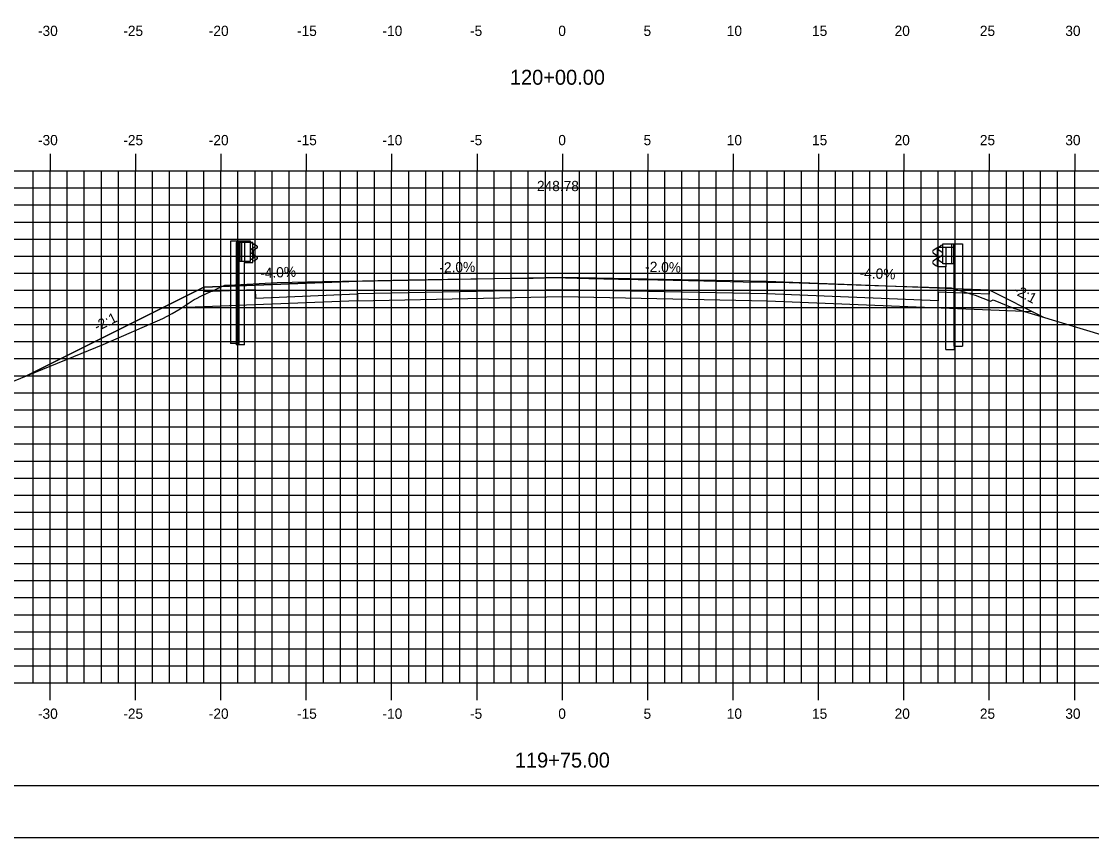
# Model space of a CAD drawing. Extents: x -22 to 1480, y -1511 to 8.
# Drawn here: x 378.2 to 440.9, y -1511.4 to -1463.6 of the extents above; entities that cross this region are included whole.
import ezdxf

# ---------------------------------------------------------------- set-up
doc = ezdxf.new("R2010")
doc.units = 0
for name, color, linetype in [('ANNOTATION', 7, 'Continuous'), ('BORDER', 7, 'Continuous'), ('D_Guardrail_Beam_Lt', 7, 'Continuous'), ('D_Guardrail_Beam_Rt', 7, 'Continuous'), ('D_Roadway_Centerline', 7, 'Continuous'), ('D_Roadway_Centerline_Text', 7, 'Continuous'), ('D_Roadway_Edge_Shoulder', 7, 'Continuous'), ('D_Roadway_Edge_TW', 7, 'Continuous'), ('D_Roadway_SlopeLines', 7, 'Continuous'), ('D_Roadway_SubGrade', 7, 'Continuous'), ('H_V ANNOTATION', 7, 'Continuous'), ('MAJOR', 7, 'Continuous'), ('MINOR', 7, 'Continuous'), ('PLOT BOUNDARY', 7, 'Continuous'), ('S_Guardrail_Beam', 7, 'Continuous'), ('S_Roadway_Centerline', 7, 'Continuous')]:
    doc.layers.add(name, color=color, linetype=linetype)

msp = doc.modelspace()

# ---------------------------------------------------------------- linework, layer by layer
at = {"layer": 'BORDER'}
msp.add_line((334.913, -1508.331), (494.913, -1508.331), dxfattribs=at)
at = {"layer": 'D_Guardrail_Beam_Lt'}
for p, q in [((390.484, -1476.449), (390.484, -1482.449)), ((390.955, -1476.449), (390.484, -1476.449)), ((391.642, -1476.449), (390.955, -1476.449)), ((390.955, -1476.449), (390.955, -1477.616)), ((391.017, -1476.449), (391.017, -1477.616)), ((391.121, -1476.449), (391.121, -1477.616)), ((391.642, -1477.616), (391.642, -1476.449)), ((391.642, -1476.532), (391.716, -1476.547)), ((391.647, -1476.997), (391.647, -1477.067)), ((391.876, -1476.797), (391.68, -1476.933)), ((391.68, -1477.132), (391.876, -1477.268)), ((391.732, -1476.554), (391.876, -1476.654)), ((390.955, -1477.616), (391.642, -1477.616)), ((390.975, -1482.449), (390.975, -1477.616)), ((391.716, -1477.518), (391.642, -1477.532)), ((391.876, -1477.411), (391.732, -1477.511)), ((390.975, -1482.449), (390.484, -1482.449))]:
    msp.add_line(p, q, dxfattribs=at)
for centre, major_axis, start_param, end_param in [((391.725, -1476.997), (-0.0789, 0), 5.323254, 6.283185), ((391.725, -1477.067), (-0.0789, 0), 6.283185, 7.243116), ((391.708, -1476.588), (0.0417, 0), 0.959931, 1.376053), ((391.825, -1476.725), (0.0877, 0), 5.323254, 7.243116), ((391.708, -1477.477), (0.0417, 0), 4.907132, 5.323254), ((391.825, -1477.34), (0.0877, 0), 5.323254, 7.243116)]:
    msp.add_ellipse(centre, major_axis=major_axis, ratio=0.995501, start_param=start_param, end_param=end_param, dxfattribs=at)
at = {"layer": 'D_Guardrail_Beam_Rt'}
for p, q in [((432.094, -1476.714), (431.95, -1476.814)), ((431.95, -1476.957), (432.146, -1477.093)), ((432.184, -1476.692), (432.11, -1476.707)), ((432.179, -1477.157), (432.179, -1477.227)), ((432.184, -1476.609), (432.871, -1476.609)), ((432.184, -1477.776), (432.184, -1476.609)), ((432.705, -1476.609), (432.705, -1477.776)), ((432.809, -1476.609), (432.809, -1477.776)), ((432.871, -1476.609), (433.342, -1476.609)), ((432.871, -1476.609), (432.871, -1477.776)), ((433.342, -1476.609), (433.342, -1482.609)), ((432.146, -1477.292), (431.95, -1477.428)), ((431.95, -1477.571), (432.094, -1477.671)), ((432.11, -1477.678), (432.184, -1477.692)), ((432.871, -1477.776), (432.184, -1477.776)), ((432.85, -1482.609), (432.85, -1477.776)), ((432.85, -1482.609), (433.342, -1482.609))]:
    msp.add_line(p, q, dxfattribs=at)
for centre, major_axis, start_param, end_param in [((432.001, -1476.885), (-0.0877, 0), 5.323254, 7.243116), ((432.118, -1476.748), (-0.0417, 0), 4.907132, 5.323254), ((432.1, -1477.157), (0.0789, 0), 0, 0.959931), ((432.001, -1477.5), (-0.0877, 0), 5.323254, 7.243116), ((432.118, -1477.637), (-0.0417, 0), 0.959931, 1.376053), ((432.1, -1477.227), (0.0789, 0), 5.323254, 6.283185)]:
    msp.add_ellipse(centre, major_axis=major_axis, ratio=0.995501, start_param=start_param, end_param=end_param, dxfattribs=at)
at = {"layer": 'D_Roadway_Centerline'}
msp.add_lwpolyline([(378.558, -1484.33), (388.913, -1479.152), (391.913, -1479.032), (397.913, -1478.792), (409.913, -1478.552), (421.913, -1478.792), (431.913, -1479.192), (434.913, -1479.312)], dxfattribs=at)
at = {"layer": 'D_Roadway_Edge_Shoulder'}
for points in [[(397.913, -1478.792), (391.913, -1479.032), (391.913, -1479.032), (388.913, -1479.152), (388.913, -1479.402), (391.913, -1479.282), (391.913, -1479.282), (391.943, -1479.781), (397.913, -1479.542)], [(421.913, -1478.792), (427.913, -1479.032), (427.913, -1479.032), (434.913, -1479.312), (434.913, -1479.562), (431.913, -1479.442), (431.913, -1479.442), (431.913, -1479.942), (421.903, -1479.542)]]:
    msp.add_lwpolyline(points, close=True, dxfattribs=at)
at = {"layer": 'D_Roadway_Edge_TW'}
msp.add_lwpolyline([(397.913, -1479.542), (397.913, -1478.792), (409.913, -1478.552), (421.913, -1478.792), (421.913, -1479.542), (409.913, -1479.302)], close=True, dxfattribs=at)
at = {"layer": 'D_Roadway_SlopeLines'}
for p, q in [((434.913, -1479.312), (438.085, -1480.899)), ((397.913, -1479.942), (386.413, -1480.402))]:
    msp.add_line(p, q, dxfattribs=at)
msp.add_lwpolyline([(388.913, -1479.152), (378.549, -1484.334)], dxfattribs=at)
at = {"layer": 'D_Roadway_SubGrade'}
msp.add_line((421.913, -1479.942), (437.413, -1480.562), dxfattribs=at)
msp.add_lwpolyline([(421.913, -1479.942), (421.913, -1479.542), (409.913, -1479.302), (397.913, -1479.542), (397.913, -1479.942), (409.913, -1479.702)], close=True, dxfattribs=at)
at = {"layer": 'MAJOR'}
for p, q in [((379.913, -1471.329), (379.913, -1472.331)), ((384.913, -1471.329), (384.913, -1472.331)), ((389.913, -1471.329), (389.913, -1472.331)), ((394.913, -1471.329), (394.913, -1472.331)), ((399.913, -1471.329), (399.913, -1472.331)), ((404.913, -1471.329), (404.913, -1472.331)), ((409.913, -1471.329), (409.913, -1472.331)), ((414.913, -1471.329), (414.913, -1472.331)), ((419.913, -1471.329), (419.913, -1472.331)), ((424.913, -1471.329), (424.913, -1472.331)), ((429.913, -1471.329), (429.913, -1472.331)), ((434.913, -1471.329), (434.913, -1472.331)), ((439.913, -1471.329), (439.913, -1472.331)), ((339.913, -1472.331), (479.913, -1472.331)), ((339.913, -1472.331), (479.913, -1472.331)), ((379.913, -1502.331), (379.913, -1472.331)), ((384.913, -1502.331), (384.913, -1472.331)), ((389.913, -1502.331), (389.913, -1472.331)), ((394.913, -1502.331), (394.913, -1472.331)), ((399.913, -1502.331), (399.913, -1472.331)), ((404.913, -1502.331), (404.913, -1472.331)), ((409.913, -1502.331), (409.913, -1472.331)), ((414.913, -1502.331), (414.913, -1472.331)), ((419.913, -1502.331), (419.913, -1472.331)), ((424.913, -1502.331), (424.913, -1472.331)), ((429.913, -1502.331), (429.913, -1472.331)), ((434.913, -1502.331), (434.913, -1472.331)), ((439.913, -1502.331), (439.913, -1472.331)), ((339.913, -1477.331), (479.913, -1477.331)), ((339.913, -1482.331), (479.913, -1482.331)), ((339.913, -1487.331), (479.913, -1487.331)), ((339.913, -1492.331), (479.913, -1492.331)), ((339.913, -1497.331), (479.913, -1497.331)), ((339.913, -1502.331), (479.913, -1502.331)), ((339.913, -1502.331), (479.913, -1502.331)), ((379.913, -1503.333), (379.913, -1502.331)), ((384.913, -1503.333), (384.913, -1502.331)), ((389.913, -1503.333), (389.913, -1502.331)), ((394.913, -1503.333), (394.913, -1502.331)), ((399.913, -1503.333), (399.913, -1502.331)), ((404.913, -1503.333), (404.913, -1502.331)), ((409.913, -1503.333), (409.913, -1502.331)), ((414.913, -1503.333), (414.913, -1502.331)), ((419.913, -1503.333), (419.913, -1502.331)), ((424.913, -1503.333), (424.913, -1502.331)), ((429.913, -1503.333), (429.913, -1502.331)), ((434.913, -1503.333), (434.913, -1502.331)), ((439.913, -1503.333), (439.913, -1502.331))]:
    msp.add_line(p, q, dxfattribs=at)
at = {"layer": 'MINOR'}
for p, q in [((378.913, -1502.331), (378.913, -1472.331)), ((380.913, -1502.331), (380.913, -1472.331)), ((381.913, -1502.331), (381.913, -1472.331)), ((382.913, -1502.331), (382.913, -1472.331)), ((383.913, -1502.331), (383.913, -1472.331)), ((385.913, -1502.331), (385.913, -1472.331)), ((386.913, -1502.331), (386.913, -1472.331)), ((387.913, -1502.331), (387.913, -1472.331)), ((388.913, -1502.331), (388.913, -1472.331)), ((390.913, -1502.331), (390.913, -1472.331)), ((391.913, -1502.331), (391.913, -1472.331)), ((392.913, -1502.331), (392.913, -1472.331)), ((393.913, -1502.331), (393.913, -1472.331)), ((395.913, -1502.331), (395.913, -1472.331)), ((396.913, -1502.331), (396.913, -1472.331)), ((397.913, -1502.331), (397.913, -1472.331)), ((398.913, -1502.331), (398.913, -1472.331)), ((400.913, -1502.331), (400.913, -1472.331)), ((401.913, -1502.331), (401.913, -1472.331)), ((402.913, -1502.331), (402.913, -1472.331)), ((403.913, -1502.331), (403.913, -1472.331)), ((405.913, -1502.331), (405.913, -1472.331)), ((406.913, -1502.331), (406.913, -1472.331)), ((407.913, -1502.331), (407.913, -1472.331)), ((408.913, -1502.331), (408.913, -1472.331)), ((410.913, -1502.331), (410.913, -1472.331)), ((411.913, -1502.331), (411.913, -1472.331)), ((412.913, -1502.331), (412.913, -1472.331)), ((413.913, -1502.331), (413.913, -1472.331)), ((415.913, -1502.331), (415.913, -1472.331)), ((416.913, -1502.331), (416.913, -1472.331)), ((417.913, -1502.331), (417.913, -1472.331)), ((418.913, -1502.331), (418.913, -1472.331)), ((420.913, -1502.331), (420.913, -1472.331)), ((421.913, -1502.331), (421.913, -1472.331)), ((422.913, -1502.331), (422.913, -1472.331)), ((423.913, -1502.331), (423.913, -1472.331)), ((425.913, -1502.331), (425.913, -1472.331)), ((426.913, -1502.331), (426.913, -1472.331)), ((427.913, -1502.331), (427.913, -1472.331)), ((428.913, -1502.331), (428.913, -1472.331)), ((430.913, -1502.331), (430.913, -1472.331)), ((431.913, -1502.331), (431.913, -1472.331)), ((432.913, -1502.331), (432.913, -1472.331)), ((433.913, -1502.331), (433.913, -1472.331)), ((435.913, -1502.331), (435.913, -1472.331)), ((436.913, -1502.331), (436.913, -1472.331)), ((437.913, -1502.331), (437.913, -1472.331)), ((438.913, -1502.331), (438.913, -1472.331)), ((339.913, -1473.331), (479.913, -1473.331)), ((339.913, -1474.331), (479.913, -1474.331)), ((339.913, -1475.331), (479.913, -1475.331)), ((339.913, -1476.331), (479.913, -1476.331)), ((339.913, -1478.331), (479.913, -1478.331)), ((339.913, -1479.331), (479.913, -1479.331)), ((339.913, -1480.331), (479.913, -1480.331)), ((339.913, -1481.331), (479.913, -1481.331)), ((339.913, -1483.331), (479.913, -1483.331)), ((339.913, -1484.331), (479.913, -1484.331)), ((339.913, -1485.331), (479.913, -1485.331)), ((339.913, -1486.331), (479.913, -1486.331)), ((339.913, -1488.331), (479.913, -1488.331)), ((339.913, -1489.331), (479.913, -1489.331)), ((339.913, -1490.331), (479.913, -1490.331)), ((339.913, -1491.331), (479.913, -1491.331)), ((339.913, -1493.331), (479.913, -1493.331)), ((339.913, -1494.331), (479.913, -1494.331)), ((339.913, -1495.331), (479.913, -1495.331)), ((339.913, -1496.331), (479.913, -1496.331)), ((339.913, -1498.331), (479.913, -1498.331)), ((339.913, -1499.331), (479.913, -1499.331)), ((339.913, -1500.331), (479.913, -1500.331)), ((339.913, -1501.331), (479.913, -1501.331))]:
    msp.add_line(p, q, dxfattribs=at)
at = {"layer": 'PLOT BOUNDARY'}
msp.add_lwpolyline([(326.82, -1511.39), (496.82, -1511.39), (496.82, -1401.39), (326.82, -1401.39)], close=True, dxfattribs=at)
at = {"layer": 'S_Guardrail_Beam'}
for p, q in [((390.8, -1476.533), (390.8, -1482.533)), ((391.292, -1476.533), (390.8, -1476.533)), ((391.782, -1476.533), (391.292, -1476.533)), ((391.292, -1476.533), (391.292, -1477.7)), ((391.782, -1477.7), (391.782, -1476.533)), ((391.782, -1476.606), (391.864, -1476.621)), ((391.795, -1477.071), (391.795, -1477.162)), ((392.024, -1476.871), (391.828, -1477.007)), ((391.88, -1476.627), (392.024, -1476.727)), ((431.774, -1476.891), (431.631, -1476.991)), ((431.631, -1477.134), (431.826, -1477.27)), ((431.873, -1476.87), (431.791, -1476.884)), ((431.873, -1476.797), (432.362, -1476.797)), ((431.873, -1477.963), (431.873, -1476.797)), ((432.362, -1476.797), (432.854, -1476.797)), ((432.362, -1476.797), (432.362, -1477.963)), ((432.854, -1476.797), (432.854, -1482.797)), ((391.292, -1482.533), (391.292, -1477.7)), ((391.292, -1477.7), (391.782, -1477.7)), ((391.864, -1477.613), (391.782, -1477.627)), ((391.828, -1477.227), (392.024, -1477.363)), ((392.024, -1477.506), (391.88, -1477.606)), ((431.826, -1477.49), (431.631, -1477.626)), ((431.631, -1477.769), (431.774, -1477.869)), ((431.86, -1477.335), (431.86, -1477.426)), ((431.791, -1477.876), (431.873, -1477.891)), ((432.362, -1477.963), (431.873, -1477.963)), ((432.362, -1482.797), (432.362, -1477.963)), ((391.292, -1482.533), (390.8, -1482.533)), ((432.362, -1482.797), (432.854, -1482.797))]:
    msp.add_line(p, q, dxfattribs=at)
for centre, major_axis, start_param, end_param in [((391.874, -1477.071), (-0.0789, 0), 5.323254, 6.283185), ((391.856, -1476.661), (0.0417, 0), 0.959931, 1.396263), ((391.974, -1476.799), (0.0877, 0), 5.323254, 7.243116), ((431.681, -1477.063), (-0.0877, 0), 5.323254, 7.243116), ((431.798, -1476.925), (-0.0417, 0), 4.886922, 5.323254), ((391.874, -1477.162), (-0.0789, 0), 6.283185, 7.243116), ((391.856, -1477.572), (0.0417, 0), 4.886922, 5.323254), ((391.974, -1477.434), (0.0877, 0), 5.323254, 7.243116), ((431.681, -1477.698), (-0.0877, 0), 5.323254, 7.243116), ((431.781, -1477.335), (0.0789, 0), 0, 0.959931), ((431.781, -1477.426), (0.0789, 0), 5.323254, 6.283185), ((431.798, -1477.835), (-0.0417, 0), 0.959931, 1.396263)]:
    msp.add_ellipse(centre, major_axis=major_axis, ratio=0.995501, start_param=start_param, end_param=end_param, dxfattribs=at)
at = {"layer": 'S_Roadway_Centerline'}
for points in [[(368.538, -1488.412), (383.024, -1482.511), (386.506, -1480.989), (387.063, -1480.696), (387.523, -1480.409), (388.356, -1479.878), (388.479, -1479.803), (388.742, -1479.669), (389.106, -1479.496), (389.431, -1479.353), (390.15, -1479.036), (390.383, -1479.025), (393.199, -1478.866), (395.863, -1478.817), (398.199, -1478.772), (400.872, -1478.722), (403.199, -1478.681), (405.881, -1478.648), (408.199, -1478.617), (408.841, -1478.602), (409.418, -1478.589), (411.466, -1478.636), (413.199, -1478.674), (415.503, -1478.722), (418.199, -1478.781), (420.496, -1478.826), (423.199, -1478.879), (425.489, -1478.957), (428.199, -1479.047), (431.981, -1479.172), (432.683, -1479.192), (432.939, -1479.272), (433.806, -1479.53), (434.088, -1479.614), (434.984, -1479.969), (435.132, -1479.888), (436.328, -1480.369), (441.643, -1481.971)], [(368.538, -1488.412), (383.024, -1482.511), (386.506, -1480.989), (387.063, -1480.696), (387.523, -1480.409), (388.356, -1479.878), (388.479, -1479.803), (388.742, -1479.669), (389.106, -1479.496), (389.431, -1479.353), (390.15, -1479.036), (390.383, -1479.025), (393.199, -1478.866), (395.863, -1478.817), (398.199, -1478.772), (400.872, -1478.722), (403.199, -1478.681), (405.881, -1478.648), (408.199, -1478.617), (408.841, -1478.602), (409.418, -1478.589), (411.466, -1478.636), (413.199, -1478.674), (415.503, -1478.722), (418.199, -1478.781), (420.496, -1478.826), (423.199, -1478.879), (425.489, -1478.957), (428.199, -1479.047), (431.981, -1479.172), (432.683, -1479.192), (432.939, -1479.272), (433.806, -1479.53), (434.088, -1479.614), (434.984, -1479.969), (435.132, -1479.888), (436.328, -1480.369)]]:
    msp.add_lwpolyline(points, dxfattribs=at)

# ---------------------------------------------------------------- texts
at = {"layer": 'ANNOTATION'}
for s, rotation, p in [('-2.0%', 1.14576, (402.716, -1478.296)), ('-2.0%', 358.85424, (414.756, -1478.249)), ('-4.0%', 2.29061, (392.229, -1478.619)), ('-4.0%', 357.70939, (427.309, -1478.607)), ('-2:1', 332.2617, (436.261, -1479.491)), ('-2:1', 26.56505, (382.665, -1481.758))]:
    msp.add_text(s, height=0.6, rotation=rotation, dxfattribs=at).set_placement(p)
at = {"layer": 'D_Roadway_Centerline'}
for s, p in [('C', (409.908, -1478.552)), ('L', (409.913, -1478.56))]:
    msp.add_text(s, height=0.0146, dxfattribs=at).set_placement(p)
at = {"layer": 'D_Roadway_Centerline_Text'}
msp.add_text('248.78', height=0.6, dxfattribs=at).set_placement((408.423, -1473.52))
at = {"layer": 'H_V ANNOTATION'}
for s, height, p in [('-30', 0.6, (379.201, -1464.431)), ('-25', 0.6, (384.198, -1464.431)), ('-20', 0.6, (389.206, -1464.431)), ('-15', 0.6, (394.37, -1464.431)), ('-10', 0.6, (399.378, -1464.431)), ('-5', 0.6, (404.504, -1464.431)), ('0', 0.6, (409.672, -1464.431)), ('5', 0.6, (414.664, -1464.431)), ('10', 0.6, (419.538, -1464.431)), ('15', 0.6, (424.53, -1464.431)), ('20', 0.6, (429.367, -1464.431)), ('25', 0.6, (434.359, -1464.431)), ('30', 0.6, (439.362, -1464.431)), ('120+00.00', 0.875, (406.839, -1467.288)), ('-30', 0.6, (379.201, -1470.831)), ('-25', 0.6, (384.198, -1470.831)), ('-20', 0.6, (389.206, -1470.831)), ('-15', 0.6, (394.37, -1470.831)), ('-10', 0.6, (399.378, -1470.831)), ('-5', 0.6, (404.504, -1470.831)), ('0', 0.6, (409.672, -1470.831)), ('5', 0.6, (414.664, -1470.831)), ('10', 0.6, (419.538, -1470.831)), ('15', 0.6, (424.53, -1470.831)), ('20', 0.6, (429.367, -1470.831)), ('25', 0.6, (434.359, -1470.831)), ('30', 0.6, (439.362, -1470.831)), ('-30', 0.6, (379.201, -1504.431)), ('-25', 0.6, (384.198, -1504.431)), ('-20', 0.6, (389.206, -1504.431)), ('-15', 0.6, (394.37, -1504.431)), ('-10', 0.6, (399.378, -1504.431)), ('-5', 0.6, (404.504, -1504.431)), ('0', 0.6, (409.672, -1504.431)), ('5', 0.6, (414.664, -1504.431)), ('10', 0.6, (419.538, -1504.431)), ('15', 0.6, (424.53, -1504.431)), ('20', 0.6, (429.367, -1504.431)), ('25', 0.6, (434.359, -1504.431)), ('30', 0.6, (439.362, -1504.431)), ('119+75.00', 0.875, (407.127, -1507.288))]:
    msp.add_text(s, height=height, dxfattribs=at).set_placement(p)

doc.saveas('drawing.dxf')
